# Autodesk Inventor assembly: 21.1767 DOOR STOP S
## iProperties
Created: 2007-07
Part Number: 21.1767 DOOR STOP S
Document SubType Name: Assembly
Designer: Andy Moles
Mass: 137.491 g
Surface Area: 92.7726 cm^2
Volume: 17.5113 cm^3
Density: 7.85157 g/cm^3
Author: Andy Moles
